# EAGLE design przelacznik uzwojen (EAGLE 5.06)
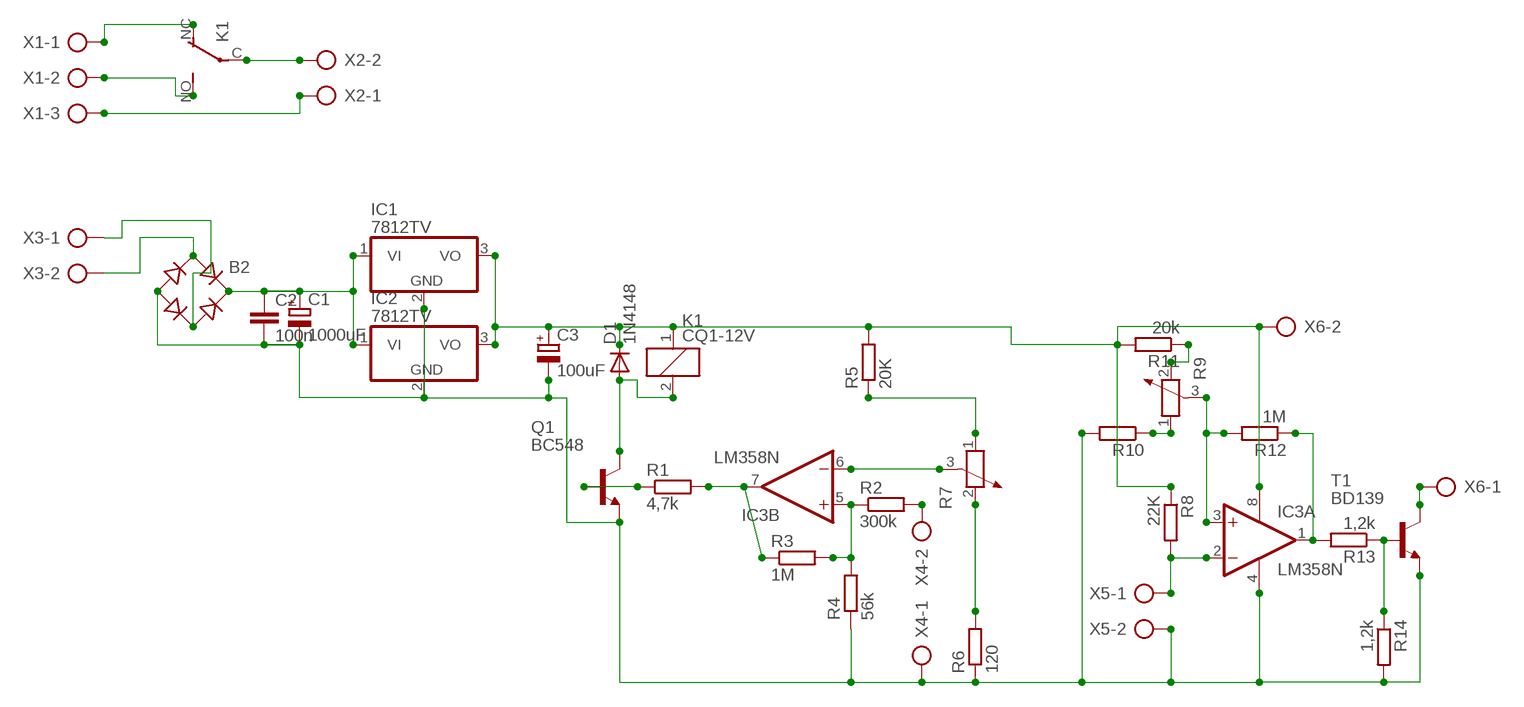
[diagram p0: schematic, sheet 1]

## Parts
B2  RB1A  [RB1A]
C1  1000uF  CPOL-EUE5-10.5  [E5-10,5]
C2  100n  C-EU025-025X050  [C025-025X050]
C3  100uF  CPOL-EUE2.5-6  [E2,5-6]
D1  1N4148  1N4148DO35-7  [DO35-7]
IC1  7812TV  [TO220V]
IC2  7812TV  [TO220V]
IC3  LM358N  [DIL08]
K1  CQ1-12V  [CQ1]
Q1  BC548  [TO92-EBC]
R1  4,7k  R-EU_0207/10  [0207/10]
R2  300k  R-EU_0411/15  [0411/15]
R3  1M  R-EU_0207/10  [0207/10]
R4  56k  R-EU_0207/10  [0207/10]
R5  20K  R-EU_0207/10  [0207/10]
R6  120  R-EU_0207/10  [0207/10]
R7  POTENTIOMETER_PT-10  [PT-10]
R8  22K  R-EU_0207/10  [0207/10]
R9  POTENTIOMETER_PT-10  [PT-10]
R10  R-EU_0207/10  [0207/10]
R11  20k  R-EU_0207/10  [0207/10]
R12  1M  R-EU_0207/10  [0207/10]
R13  1,2k  R-EU_0207/10  [0207/10]
R14  1,2k  R-EU_0207/10  [0207/10]
T1  BD139  [TO126]
X1  AK500/3  [AK500/3]
X2  AK500/2-H  [AK500/2-H]
X3  AK500/2-H  [AK500/2-H]
X4  AK500/2-H  [AK500/2-H]
X5  AK500/2-H  [AK500/2-H]
X6  AK500/2-H  [AK500/2-H]

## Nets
N$1: B2.+ C1.+ C2.1 IC1.1(VI) IC2.1(VI)
N$2: B2.- C1.- C2.2 C3.- IC1.2(GND) IC2.2(GND) IC3.4(P:V-) Q1.E R4.1 R6.1 R10.2 R14.2 T1.1(E) X4.1 X5.2
N$3: X1.3 X2.1
N$4: K1.NO(2:S) X1.2
N$5: C3.+ D1.C IC1.3(VO) IC2.3(VO) IC3.8(P:V+) K1.1 R5.2 R8.1 R11.2 X6.2
N$6: D1.A K1.2 Q1.C
N$7: Q1.B R1.1
N$8: K1.NC(2:O) X1.1
N$9: K1.C(2:P) X2.2
N$10: IC3.7(B:OUT) R1.2 R3.1
N$11: IC3.5(B:+IN) R2.1 R3.2 R4.2
N$12: R2.2 X4.2
N$13: R6.2 R7.2
N$14: B2.AC2 X3.1
N$15: B2.AC1 X3.2
N$16: IC3.6(B:-IN) R7.3
N$17: R5.1 R7.1
N$18: IC3.2(A:-IN) R8.2 X5.1
N$19: R9.2 R11.1
N$20: IC3.1(A:OUT) R12.1 R13.2
N$21: R9.1 R10.1
N$22: IC3.3(A:+IN) R9.3 R12.2
N$24: R13.1 R14.1 T1.3(B)
N$26: T1.2(C) X6.1

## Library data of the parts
B2 = rectifier:RB1A: RECTIFIER 1 A
C1 C3 = rcl:CPOL-EU: POLARIZED CAPACITOR, European symbol
C2 = rcl:C-EU: CAPACITOR, European symbol
D1 = diode:1N4148: DIODE
IC1 IC2 = linear:78*: Positive VOLTAGE REGULATOR Source: http://cache.national.com/ds/LM/LM78L05.pdf http://www.fairchildsemi.com/ds/LM/LM7805.pdf
IC3 = linear:LM358: OP AMP also LM158; LM258; LM2904 Source: http://cache.national.com/ds/LM/LM158.pdf
K1 = relay:CQ1-12V: AUTOMOTIVE QUIET RELAY NAiS Source: http://www.mew-europe.com/.. en_ds_61208_0000.pdf
Q1 = transistor-npn:BC548*: NPN Transistor
R1-R6 R8 R10-R14 = rcl:R-EU_: RESISTOR, European symbol
R7 R9 = rcl:POTENTIOMETER_: Potentiometer
T1 = transistor:BD139: NPN TRANSISTOR
X1 = con-ptr500:AK500/3: CONNECTOR
X2-X6 = con-ptr500:AK500/2-H: CONNECTOR

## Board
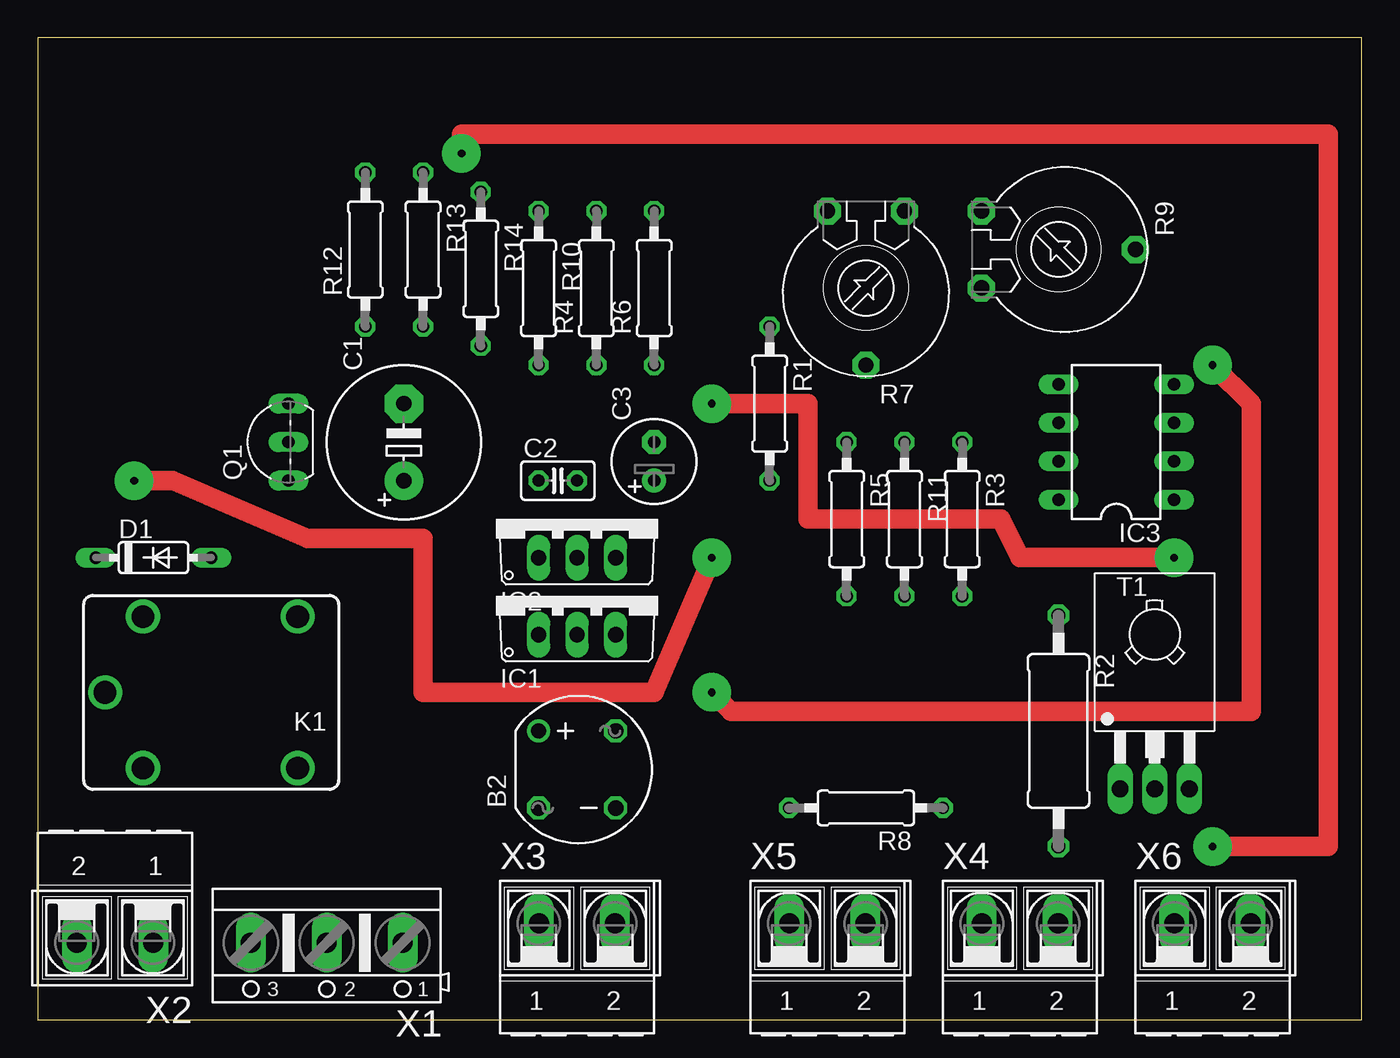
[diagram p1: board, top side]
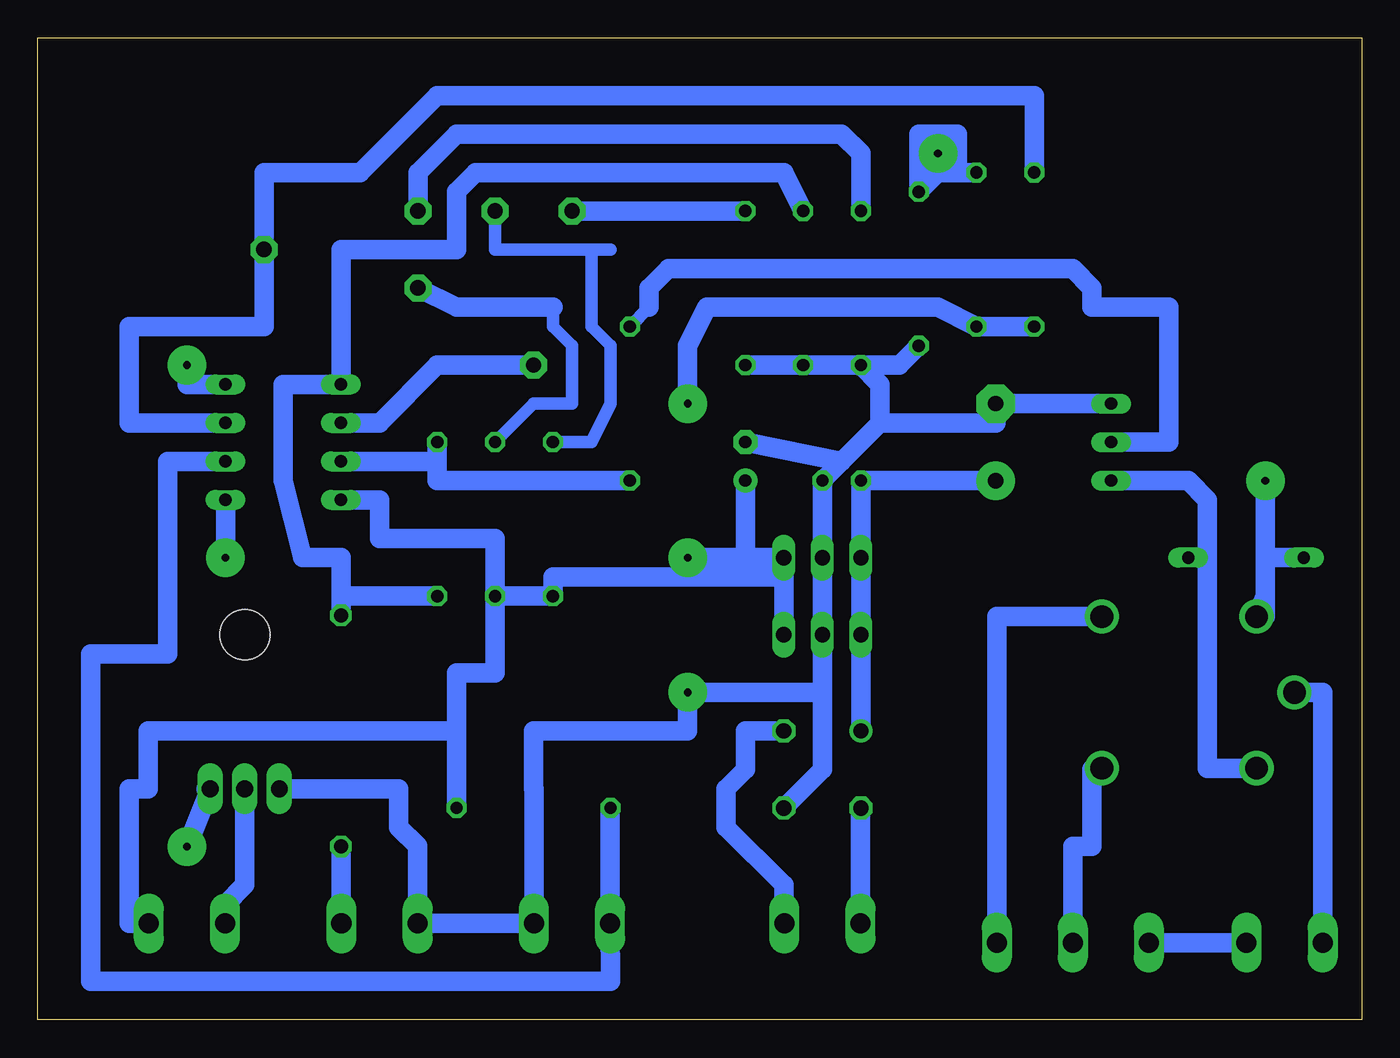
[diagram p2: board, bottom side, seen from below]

Size 87.3 x 64.76 mm. Coordinates in mm from the lower left corner, seen from the top.
Outline: 0,0 87.3,0 87.3,64.76 0,64.76 0,0
Copper layers (1*16): Top 0.035mm / dielectric 1.5mm / Bottom 0.035mm
Design rules "default": minimum track width 10mil, minimum drill 24mil, track to track 8mil, track to pad 8mil, pad to pad 8mil, via to via 8mil, smd to smd 8mil, copper to edge 40mil, drill to drill 8mil, minimum pad ring 10mil, minimum via ring 8mil, stop-mask expansion 4mil, vias tented up to drill 0mil, thermal gap 10mil

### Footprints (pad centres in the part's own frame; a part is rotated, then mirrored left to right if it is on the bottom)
RB1A = drill 1.016 round: + -2.54,2.54 | drill 1.016 octagon: - 2.54,-2.54; AC1 2.54,2.54; AC2 -2.54,-2.54
E5-10,5 = drill 1.016 pad 2.54 round: + -2.54,0 | drill 1.016 pad 2.54 octagon: - 2.54,0
C025-025X050 = drill 0.813 octagon: 1 -1.27,0; 2 1.27,0
E2,5-6 = drill 0.813 pad 1.6 round: + -1.27,0 | drill 0.813 pad 1.6 octagon: - 1.27,0
DO35-7 = drill 0.813 long: A 3.81,0; C -3.81,0
TO220V = drill 1.016 long: 1 -2.54,-2.54; 2 0,-2.54; 3 2.54,-2.54
DIL08 = drill 0.813 long: 1 -3.81,-3.81; 2 -1.27,-3.81; 3 1.27,-3.81; 4 3.81,-3.81; 5 3.81,3.81; 6 1.27,3.81; 7 -1.27,3.81; 8 -3.81,3.81
CQ1 = drill 1.5 round: 1 4.5,-5; 2 4.5,5; C 7,0; NC -5.7,-5; NO -5.7,5
TO92-EBC = drill 0.813 long: B 0,-1.27; C -2.54,-1.27; E 2.54,-1.27
0207/10 = drill 0.813 octagon: 1 -5.08,0; 2 5.08,0
0411/15 = drill 0.914 octagon: 1 -7.62,0; 2 7.62,0
PT-10 = drill 1.016 pad 1.778 octagon: 1 -2.54,-5.08; 2 2.54,-5.08; 3 0,5.08
TO126 = drill 1.118 long: 1 -2.286,-5.08; 2 0,-5.08; 3 2.286,-5.08 | hole 3.302: 0,5.08
AK500/3 = drill 1.321 long: 1 -5.004,0; 2 0,0; 3 5.004,0
AK500/2-H = drill 1.321 long: 1 -2.515,0; 2 2.515,0

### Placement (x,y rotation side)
B2  35.56,16.51 0 top
C1  24.13,38.1 90 top
C2  34.29,35.56 0 top
C3  40.64,36.83 90 top
D1  7.62,30.48 0 top
IC1  35.56,27.94 0 top
IC2  35.56,33.02 0 top
IC3  71.12,38.1 90 top
K1  11.43,21.59 180 top
Q1  15.24,38.1 90 top
R1  48.26,40.64 270 top
R2  67.31,19.05 270 top
R3  60.96,33.02 270 top
R4  36.83,48.26 90 top
R5  53.34,33.02 270 top
R6  40.64,48.26 90 top
R7  54.61,48.26 180 top
R8  54.61,13.97 180 top
R9  67.31,50.8 270 top
R10  33.02,48.26 270 top
R11  57.15,33.02 270 top
R12  21.59,50.8 90 top
R13  25.4,50.8 270 top
R14  29.21,49.53 270 top
T1  73.66,20.32 0 top
X1  19.05,5.08 180 top
X2  5.08,5.08 180 top
X3  35.56,6.35 0 top
X4  64.77,6.35 0 top
X5  52.07,6.35 0 top
X6  77.47,6.35 0 top

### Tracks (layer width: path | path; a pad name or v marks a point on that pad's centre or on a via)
N$1
  Bottom 1.27: B2.+ IC1.1 IC2.1 C2.1 C1.+
N$2  (via drill 0.5 pad 2.54)
  Top 1.27: v77.47,43.18 80.01,40.64 80.01,20.32 45.72,20.32 v44.45,21.59
  Bottom 1.27: 34.29,36.83 C2.2 IC2.2 IC1.2 35.56,21.59 | 34.29,36.83 31.75,39.37 | 31.75,39.37 24.13,39.37 C1.- Q1.E | 34.29,36.83 C3.- | 54.58,15.21 X5.2 X4.1 62.25,11.45 63.5,12.7 63.5,15.24 T1.1 | 54.61,15.24 54.58,15.21 | R6.1 R4.1 R10.2 | R10.2 30.48,43.18 R14.2 | 31.75,39.37 31.75,41.91 R10.2 | 54.58,15.21 54.61,15.21 54.61,15.24 | 54.61,15.24 54.61,19.05 44.45,19.05 v44.45,21.59 35.56,21.59 | 35.56,21.59 35.56,16.51 B2.- | IC3.4 77.47,41.91 v77.47,43.18
N$3
  Bottom 1.27: X2.1 X1.3
N$4
  Bottom 1.27: X1.2 19.05,11.43 17.78,11.43 17.78,16.51 17.13,16.51 K1.NO
N$5  (via drill 0.5 pad 2.54)
  Top 1.27: v44.45,30.48 40.64,21.59 25.4,21.59 25.4,31.75 17.78,31.75 8.89,35.56 v6.35,35.56
  Bottom 1.27: 6.35,27.94 6.35,26.59 K1.1 6.35,27.94 | 6.35,27.94 6.35,30.48 | 6.35,30.48 6.35,31.75 | 38.1,29.21 IC1.3 | 6.35,30.48 D1.C | 40.64,30.48 40.64,29.21 | 40.64,30.48 C3.+ | IC2.3 39.37,29.21 | R11.2 R5.2 53.34,29.21 40.64,29.21 | IC3.8 64.77,34.29 64.77,31.75 57.15,31.75 R11.2 | X6.2 81.28,6.35 81.28,15.24 80.01,15.24 80.01,19.05 59.69,19.05 | 59.69,19.05 R8.1 | R11.2 57.15,22.86 59.69,22.86 59.69,19.05 | 39.37,29.21 40.64,29.21 | 39.37,29.21 39.37,30.48 40.64,30.48 | IC2.3 40.64,30.48 | IC2.3 38.1,29.21 | 38.1,29.21 40.64,29.21 | 6.35,27.94 v6.35,35.56 | v44.45,30.48 IC2.3
N$6
  Bottom 1.27: K1.2 10.16,16.59 10.16,30.48 | 10.16,30.48 D1.A | 10.16,30.48 10.16,34.29 11.43,35.56 Q1.C
N$7
  Bottom 0.813: R1.1 46.99,46.99
  Bottom 1.27: Q1.B 12.7,38.1 12.7,46.99 17.78,46.99 17.78,48.26 19.05,49.53 45.72,49.53 46.99,48.26 46.99,46.99
N$8
  Bottom 1.27: K1.NC 24.05,26.59 X1.1
N$9
  Bottom 1.27: K1.C 2.56,21.59 X2.2
N$10
  Bottom 1.27: R1.2 60.96,35.56 60.96,36.83 | 60.96,36.83 R3.1 | 60.96,36.83 IC3.7
N$11
  Bottom 1.27: R3.2 67.31,27.94 R2.1 67.31,30.48 69.85,30.48 71.12,35.56 71.12,41.91 IC3.5 67.31,50.8 59.69,50.8 59.69,54.61 58.42,55.88 38.1,55.88 R4.2
N$12
  Bottom 1.27: R2.2 67.31,6.38 X4.2
N$13
  Bottom 1.27: R6.2 R7.2
N$14
  Bottom 1.27: B2.AC2 33.04,13.97 X3.1
N$15
  Bottom 1.27: B2.AC1 40.64,19.05 40.64,16.51 41.91,15.24 41.91,12.7 38.1,8.89 38.1,6.38 X3.2
N$16
  Bottom 1.27: R7.3 60.96,43.18 64.77,39.37 IC3.6
N$17
  Bottom 0.813: R7.1 57.15,50.8 50.8,50.8 | 50.8,50.8 49.53,50.8 | R5.1 50.8,38.1 49.53,40.64 49.53,44.45 50.8,45.72 50.8,50.8
N$18
  Bottom 1.27: R8.2 49.55,13.95 X5.1 49.53,2.54 83.82,2.54 83.82,24.13 78.74,24.13 78.74,36.83 IC3.2
N$19
  Bottom 0.813: 53.34,46.99 53.34,45.72 52.07,44.45 52.07,40.64 54.61,40.64 R11.1
  Bottom 1.27: R9.2 59.69,46.99 53.34,46.99
N$20  (via drill 0.5 pad 2.54)
  Top 1.27: v44.45,40.64 50.8,40.64 50.8,33.02 63.5,33.02 64.77,30.48 v74.93,30.48
  Bottom 1.27: R12.1 R13.2 27.94,46.99 43.18,46.99 44.45,44.45 v44.45,40.64 | v74.93,30.48 IC3.1
N$21
  Bottom 1.27: R10.1 33.02,57.15 34.29,58.42 59.69,58.42 62.23,55.88 R9.1
N$22
  Bottom 1.27: R12.2 21.59,60.96 60.96,60.96 66.04,55.88 72.39,55.88 R9.3 72.39,45.72 81.28,45.72 81.28,39.37 IC3.3
N$24  (via drill 0.5 pad 2.54)
  Top 1.27: v77.47,11.43 85.09,11.43 85.09,58.42 27.94,58.42 v27.94,57.15
  Bottom 1.27: 76.2,15.24 T1.3 v77.47,11.43 | R13.1 26.67,55.88 | 27.94,55.88 R14.1 29.21,55.88 | 29.21,55.88 29.21,57.15 | 27.94,58.42 26.67,58.42 26.67,55.88 | 29.21,58.42 27.94,58.42 | 26.67,55.88 27.94,55.88 | 27.94,55.88 29.21,55.88 | 29.21,55.88 v27.94,57.15 | v27.94,57.15 29.21,57.15 | 29.21,58.42 29.21,57.15 | 27.94,55.88 29.21,58.42 | 27.94,55.88 v27.94,57.15 | v27.94,57.15 27.94,58.42
N$25  (via drill 0.5 pad 2.54)
  other vias: 77.47,11.43
N$26
  Bottom 1.27: X6.1 74.95,7.59 73.66,8.89 T1.2
N$31  (via drill 0.5 pad 2.54)
  other vias: 77.47,43.18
